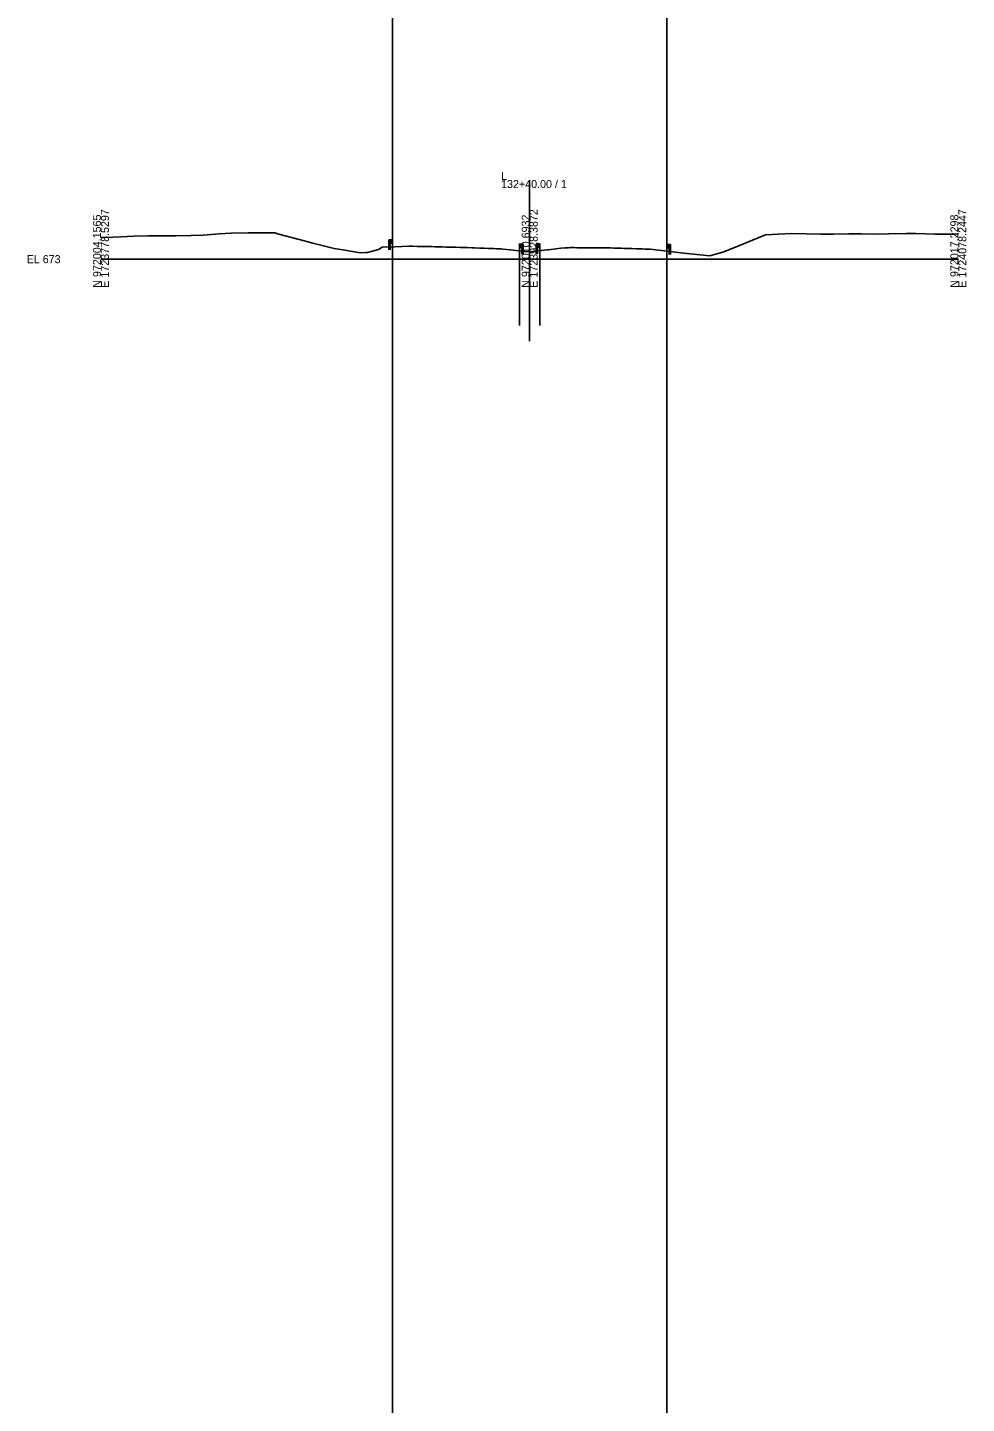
# Model space of a CAD drawing. Extents: x -26 to 303, y -29 to 15026.
# Drawn here: x -25.7 to 302.8, y 13099.5 to 13581.1 of the extents above; entities that cross this region are included whole.
import ezdxf

# ---------------------------------------------------------------- set-up
doc = ezdxf.new("R2010")
doc.units = 0
for name, color, linetype in [('Exist Cross Section Cell', 7, 'Continuous'), ('Exist XS Center Line Elevation Label', 7, 'Continuous'), ('Exist XS Ground Line', 7, 'Continuous'), ('Scratch_Level_0', 7, 'Continuous'), ('Typical Guardrail CELL', 7, 'Continuous')]:
    doc.layers.add(name, color=color, linetype=linetype)

msp = doc.modelspace()

# ---------------------------------------------------------------- linework, layer by layer
at = {"layer": 'Exist Cross Section Cell'}
for p, q in [((150, 13500), (150, 13527.69)), ((0, 13500), (150, 13500)), ((150, 13500), (300, 13500))]:
    msp.add_line(p, q, dxfattribs=at)
at = {"layer": 'Exist XS Ground Line'}
msp.add_lwpolyline([(0, 13507.6), (1.48, 13507.63), (7.02, 13507.86), (11.49, 13508.01), (16.61, 13508.13), (21.5, 13508.15), (26.2, 13508.19), (31.51, 13508.23), (35.79, 13508.41), (41.52, 13508.83), (45.39, 13509.11), (51.53, 13509.23), (59.52, 13509.2), (60.88, 13509.19), (62.19, 13508.8), (71.55, 13506.28), (74.16, 13505.58), (81.56, 13503.73), (84.65, 13503.22), (90.7, 13502.25), (92.65, 13502.33), (93.29, 13502.35), (95.02, 13502.83), (97.12, 13503.43), (98.34, 13504.19), (102.79, 13504.34), (105.39, 13504.44), (107.68, 13504.52), (108.38, 13504.51), (109.09, 13504.5), (110.68, 13504.48), (111.39, 13504.48), (111.77, 13504.47), (113.19, 13504.43), (114.68, 13504.4), (115.7, 13504.38), (116.81, 13504.35), (118.2, 13504.33), (119.48, 13504.28), (120.69, 13504.24), (122.08, 13504.21), (123.12, 13504.2), (124.06, 13504.17), (125.66, 13504.12), (127.22, 13504.08), (128.17, 13504.06), (129.85, 13504), (130.68, 13503.97), (132.46, 13503.9), (133.16, 13503.88), (134.1, 13503.84), (135.65, 13503.78), (137.49, 13503.71), (138.45, 13503.67), (140.06, 13503.6), (140.76, 13503.52), (143.18, 13503.27), (148.21, 13502.74), (149.89, 13502.57), (156.07, 13503.24), (156.44, 13503.28), (157.39, 13503.38), (160.94, 13503.82), (162.51, 13504.01), (163.31, 13504.02), (163.63, 13504.02), (164.26, 13504.03), (165.21, 13504.03), (165.74, 13504.03), (166.5, 13504.02), (168.23, 13504.02), (169.83, 13504.02), (170.75, 13504.02), (171.75, 13504.01), (173.24, 13504), (174.63, 13504), (175.75, 13503.99), (176.48, 13503.98), (177.06, 13503.97), (177.5, 13503.96), (178.23, 13503.93), (179.4, 13503.89), (180.72, 13503.85), (182.18, 13503.82), (183.22, 13503.79), (184.18, 13503.76), (185.73, 13503.7), (187.42, 13503.66), (188.22, 13503.64), (188.97, 13503.61), (189.31, 13503.6), (190.38, 13503.55), (190.75, 13503.53), (191.17, 13503.51), (192.16, 13503.47), (197.18, 13502.89), (200.04, 13502.57), (202.95, 13502.25), (213.09, 13501.15), (215.49, 13501.82), (217.59, 13502.43), (220.8, 13503.7), (232.54, 13508.54), (236.99, 13508.77), (241.7, 13509.03), (246.79, 13508.91), (251.71, 13508.76), (256.38, 13508.77), (261.72, 13508.89), (265.97, 13508.82), (271.73, 13508.78), (275.56, 13508.86), (281.74, 13508.95), (285.15, 13509.02), (291.75, 13508.75), (298.94, 13508.77), (300, 13508.82)], dxfattribs=at)
at = {"layer": 'Scratch_Level_0'}
for p, q in [((102, 15009.56), (102, -28.7)), ((198, 15009.56), (198, -28.7)), ((146.46, 13505.5), (146.46, 13476.8)), ((153.54, 13505.5), (153.54, 13476.8)), ((150, 13500), (150, 13471.3))]:
    msp.add_line(p, q, dxfattribs=at)
at = {"layer": 'Typical Guardrail CELL'}
for p, q in [((101.18, 13506.75), (100.68, 13506.75)), ((100.68, 13506.75), (100.68, 13504.27)), ((101.18, 13504.27), (100.68, 13504.27)), ((100.68, 13504.27), (100.68, 13503.26)), ((101.18, 13506.75), (101.18, 13504.27)), ((101.18, 13506.75), (101.68, 13506.75)), ((101.18, 13505.59), (101.68, 13505.59)), ((101.18, 13504.27), (101.18, 13503.26)), ((101.68, 13506.75), (101.68, 13505.59)), ((101.68, 13506.75), (101.97, 13506.55)), ((101.68, 13506.22), (101.97, 13506.42)), ((101.68, 13506.17), (101.68, 13506.22)), ((101.68, 13506.17), (101.68, 13506.13)), ((101.68, 13506.13), (101.97, 13505.92)), ((101.68, 13505.59), (101.97, 13505.8)), ((146.78, 13505.27), (146.49, 13505.07)), ((146.78, 13504.74), (146.49, 13504.94)), ((146.78, 13504.65), (146.49, 13504.44)), ((146.78, 13504.11), (146.49, 13504.32)), ((147.28, 13505.27), (146.78, 13505.27)), ((146.78, 13505.27), (146.78, 13504.11)), ((146.78, 13504.69), (146.78, 13504.74)), ((146.78, 13504.69), (146.78, 13504.65)), ((147.28, 13504.11), (146.78, 13504.11)), ((147.28, 13505.27), (147.28, 13502.79)), ((147.28, 13505.27), (147.78, 13505.27)), ((147.78, 13505.27), (147.78, 13502.79)), ((152.72, 13505.31), (152.22, 13505.31)), ((152.22, 13505.31), (152.22, 13502.82)), ((152.72, 13505.31), (152.72, 13502.82)), ((152.72, 13505.31), (153.22, 13505.31)), ((152.72, 13504.15), (153.22, 13504.15)), ((153.22, 13505.31), (153.22, 13504.15)), ((153.22, 13505.31), (153.51, 13505.11)), ((153.22, 13504.77), (153.51, 13504.98)), ((153.22, 13504.73), (153.22, 13504.77)), ((153.22, 13504.73), (153.22, 13504.68)), ((153.22, 13504.68), (153.51, 13504.48)), ((153.22, 13504.15), (153.51, 13504.35)), ((198.32, 13505.14), (198.03, 13504.93)), ((198.32, 13504.6), (198.03, 13504.81)), ((198.32, 13504.51), (198.03, 13504.31)), ((198.32, 13503.98), (198.03, 13504.18)), ((198.82, 13505.14), (198.32, 13505.14)), ((198.32, 13505.14), (198.32, 13503.98)), ((198.32, 13504.56), (198.32, 13504.6)), ((198.32, 13504.56), (198.32, 13504.51)), ((198.82, 13503.98), (198.32, 13503.98)), ((198.82, 13505.14), (198.82, 13502.65)), ((198.82, 13505.14), (199.32, 13505.14)), ((199.32, 13505.14), (199.32, 13502.65)), ((147.28, 13502.79), (147.78, 13502.79)), ((147.28, 13502.79), (147.28, 13501.78)), ((147.78, 13502.79), (147.78, 13501.78)), ((152.72, 13502.82), (152.22, 13502.82)), ((152.22, 13502.82), (152.22, 13501.81)), ((152.72, 13502.82), (152.72, 13501.81)), ((198.82, 13502.65), (199.32, 13502.65)), ((198.82, 13502.65), (198.82, 13501.64)), ((199.32, 13502.65), (199.32, 13501.64))]:
    msp.add_line(p, q, dxfattribs=at)
for centre, start, end in [((101.92, 13506.49), 304.9888, 54.997), ((101.92, 13505.86), 304.9634, 54.9941), ((146.54, 13505.01), 125.003, 235.0112), ((146.54, 13504.38), 125.0059, 235.0366), ((153.46, 13505.04), 304.9888, 54.997), ((153.46, 13504.41), 304.9634, 54.9941), ((198.08, 13504.87), 125.003, 235.0112), ((198.08, 13504.24), 125.0059, 235.0366)]:
    msp.add_arc(centre, 0.0776, start, end, dxfattribs=at)

# ---------------------------------------------------------------- texts
at = {"layer": 'Exist Cross Section Cell'}
for s, p in [('132+40.00 / 1', (140, 13524.89)), ('L', (140, 13527.69)), ('EL 673', (-26, 13498.6))]:
    msp.add_text(s, height=2.8, dxfattribs=at).set_placement(p)
for s, p in [('N 972004.1565', (0, 13490)), ('E 1723778.5297', (2.8, 13490)), ('N 972010.6932', (150, 13490)), ('E 1723928.3872', (152.8, 13490)), ('N 972017.2298', (300, 13490)), ('E 1724078.2447', (302.8, 13490))]:
    msp.add_text(s, height=2.8, rotation=90, dxfattribs=at).set_placement(p)
at = {"layer": 'Exist XS Center Line Elevation Label'}
msp.add_text('675.58', height=0.18, dxfattribs=at).set_placement((149.62, 13502.09))

doc.saveas('drawing.dxf')
